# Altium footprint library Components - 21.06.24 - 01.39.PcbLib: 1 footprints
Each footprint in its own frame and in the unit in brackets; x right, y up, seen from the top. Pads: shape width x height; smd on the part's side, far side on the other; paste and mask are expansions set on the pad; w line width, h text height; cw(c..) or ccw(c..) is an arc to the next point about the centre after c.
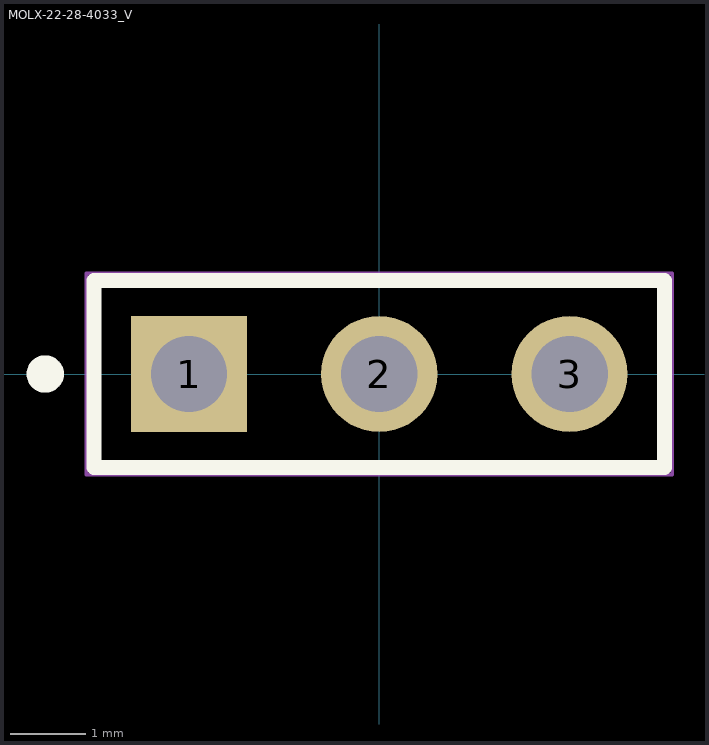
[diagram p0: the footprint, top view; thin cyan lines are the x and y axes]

## MOLX-22-28-4033_V [mm] "THD, 3-Leads, Body 7.62x2.49mm, Pitch 2.54mm"
height 8.38
pads (3):
  rect 1.55x1.55 hole 1.02: 1(-2.54,0)
  round 1.55 hole 1.02: 2(0,0) 3(2.54,0)
Top Overlay:
  circle w0.25: c-4.46,0 r0.125
  lines w0.2: -3.81,-1.245 3.81,-1.245 3.81,1.245 -3.81,1.245 -3.81,-1.245
Mechanical 13:
  lines w0.1: -3.81,-1.245 3.81,-1.245 3.81,1.245 -3.81,1.245 -3.81,-1.245
Mechanical 15:
  lines w0.05: -3.91,-1.345 -3.91,1.345 3.91,1.345 3.91,-1.345 -3.91,-1.345
  lines w0.1: -0.5,0 0.5,0 ; 0,-0.5 0,0.5
3D body "022284033.stp": height 8.38, standoff -3.18, extent -3.81,-1.245 3.81,1.245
